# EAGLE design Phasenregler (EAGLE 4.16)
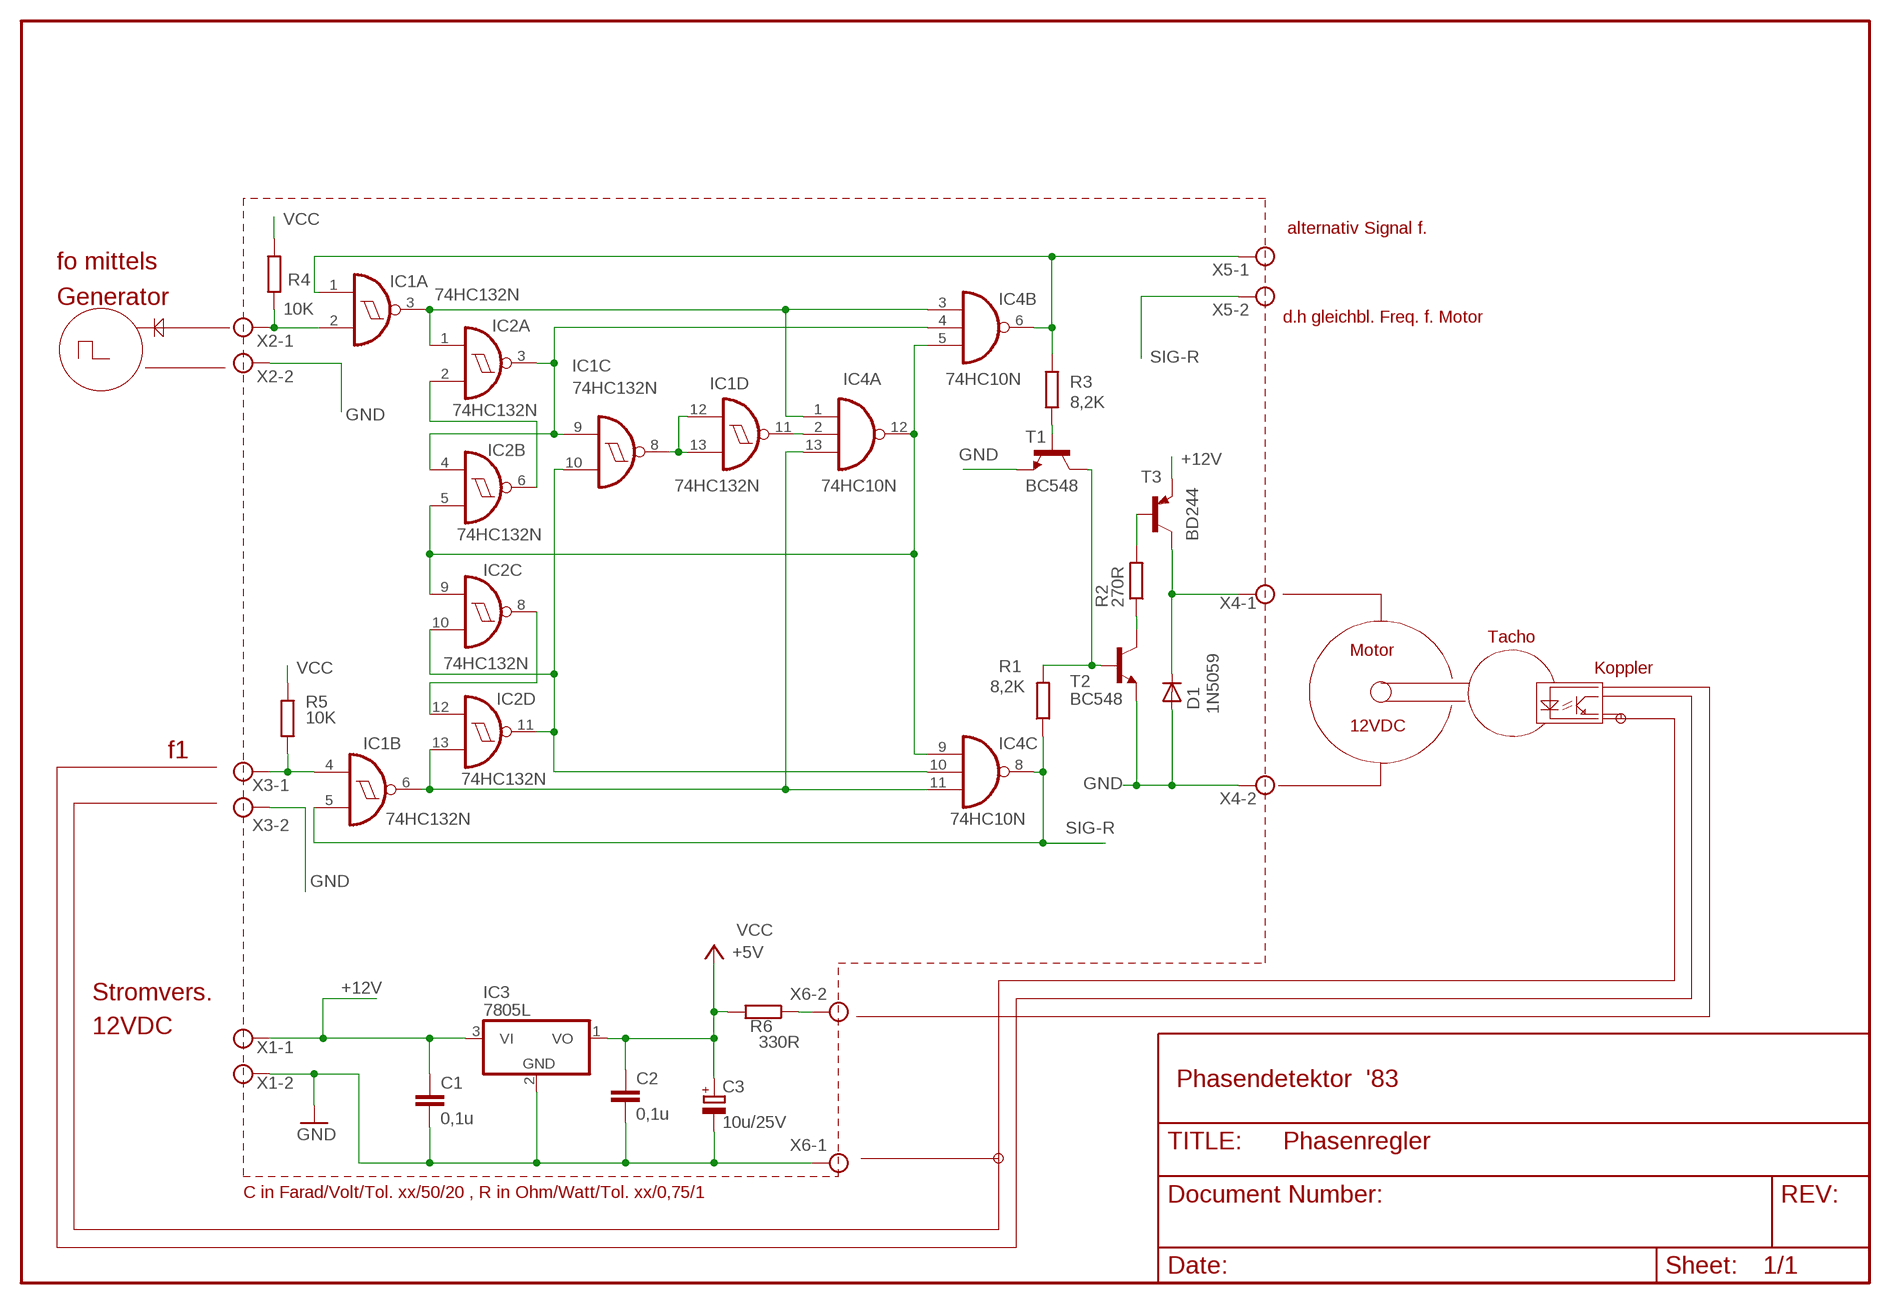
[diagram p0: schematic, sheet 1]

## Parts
C1  0,1u  C-EU050-025X075  [C050-025X075]
C2  0,1u  C-EU050-025X075  [C050-025X075]
C3  10u/25V  CPOL-EUE2-5  [E2-5]
D1  1N5059  [DO204-10]
IC1  74HC132N  [DIL14]
IC2  74HC132N  [DIL14]
IC3  7805L  [TO92]
IC4  74HC10N  [DIL14]
R1  8,2K  R-EU_0207/10  [0207/10]
R2  270R  R-EU_0207/10  [0207/10]
R3  8,2K  R-EU_0207/10  [0207/10]
R4  10K  R-EU_0207/10  [0207/10]
R5  10K  R-EU_0207/10  [0207/10]
R6  330R  R-EU_0207/10  [0207/10]
T1  BC548  [TO92]
T2  BC548  [TO92]
T3  BD244  [TO220]
X1  AK300/2  [AK300/2]
X2  AK300/2  [AK300/2]
X3  AK300/2  [AK300/2]
X4  AK300/2  [AK300/2]
X5  AK300/2  [AK300/2]
X6  AK300/2  [AK300/2]

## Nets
+12V: C1.1 IC3.3(VI) T3.3(E) X1.1
GND: C1.2 C2.2 C3.- D1.A IC3.2(GND) T1.1(E) T2.1(E) X1.2 X2.2 X3.2 X4.2 X6.1
N$1: IC2.2(A:I1) IC2.6(B:O)
N$2: IC1.9(C:I0) IC2.3(A:O) IC2.4(B:I0) IC4.4(B:I1)
N$3: IC2.5(B:I1) IC2.9(C:I0) IC4.5(B:I2) IC4.9(C:I0) IC4.12(A:O)
N$4: IC1.8(C:O) IC1.12(D:I0) IC1.13(D:I1)
N$5: IC2.8(C:O) IC2.12(D:I0)
N$6: IC1.10(C:I1) IC2.10(C:I1) IC2.11(D:O) IC4.10(C:I1)
N$7: IC1.11(D:O) IC4.2(A:I1)
N$8: IC1.3(A:O) IC2.1(A:I0) IC4.1(A:I0) IC4.3(B:I0)
N$9: IC1.6(B:O) IC2.13(D:I1) IC4.11(C:I2) IC4.13(A:I2)
N$11: IC1.1(A:I0) IC4.6(B:O) R3.2 X5.1
N$13: R1.2 T1.3(C) T2.2(B)
N$14: R2.1 T2.3(C)
N$15: R2.2 T3.1(B)
N$16: R3.1 T1.2(B)
N$17: IC1.4(B:I0) R5.1 X3.1
N$18: IC1.2(A:I1) R4.1 X2.1
N$19: D1.C T3.2(C) X4.1
N$20: R6.1 X6.2
SIG-R: IC1.5(B:I1) IC4.8(C:O) R1.1 X5.2
VCC: C2.1 C3.+ IC3.1(VO) R4.2 R5.2 R6.2 ; supply symbol labelled +5V

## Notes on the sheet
- alternativ Signal f.
- fo mittels
- Generator
- d.h gleichbl. Freq. f. Motor
- Tacho
- Motor
- Koppler
- 12VDC
- f1
- Stromvers.
- 12VDC
- Phasendetektor  '83
- C in Farad/Volt/Tol. xx/50/20 , R in Ohm/Watt/Tol. xx/0,75/1

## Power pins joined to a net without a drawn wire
GND: IC1.7(P:GND) IC2.7(P:GND) IC4.7(P:GND)
VCC: IC1.14(P:VCC) IC2.14(P:VCC) IC4.14(P:VCC)

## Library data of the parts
C1 C2 = rcl:C-EU: CAPACITOR, European symbol
C3 = rcl:CPOL-EU: POLARIZED CAPACITOR, European symbol
D1 = diode:1N5059: DIODE
IC1 IC2 = 74xx-eu:74*132: Quad 2-input NAND schmitt trigger
IC3 = linear:78*: Positive VOLTAGE REGULATOR Source: http://cache.national.com/ds/LM/LM78L05.pdf http://www.fairchildsemi.com/ds/LM/LM7805.pdf
IC4 = 74xx-eu:74*10: Triple 3-input NAND gate
R1-R6 = rcl:R-EU_: RESISTOR, European symbol
T1 T2 = transistor-mix:BC548: NPN TRANSISTOR
T3 = transistor-mix:BD244: PNP TRANSISTOR
X1-X6 = con-ptr500:AK300/2: CONNECTOR

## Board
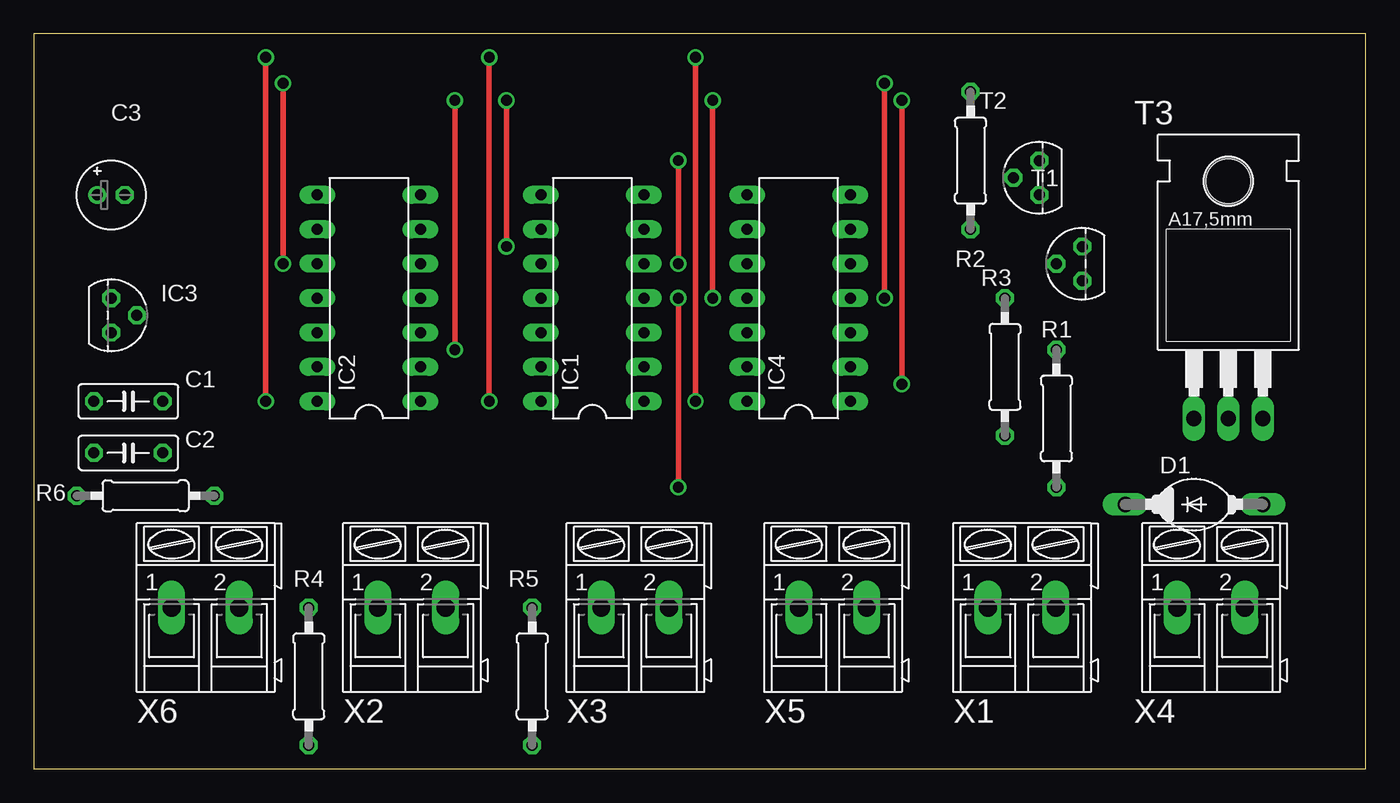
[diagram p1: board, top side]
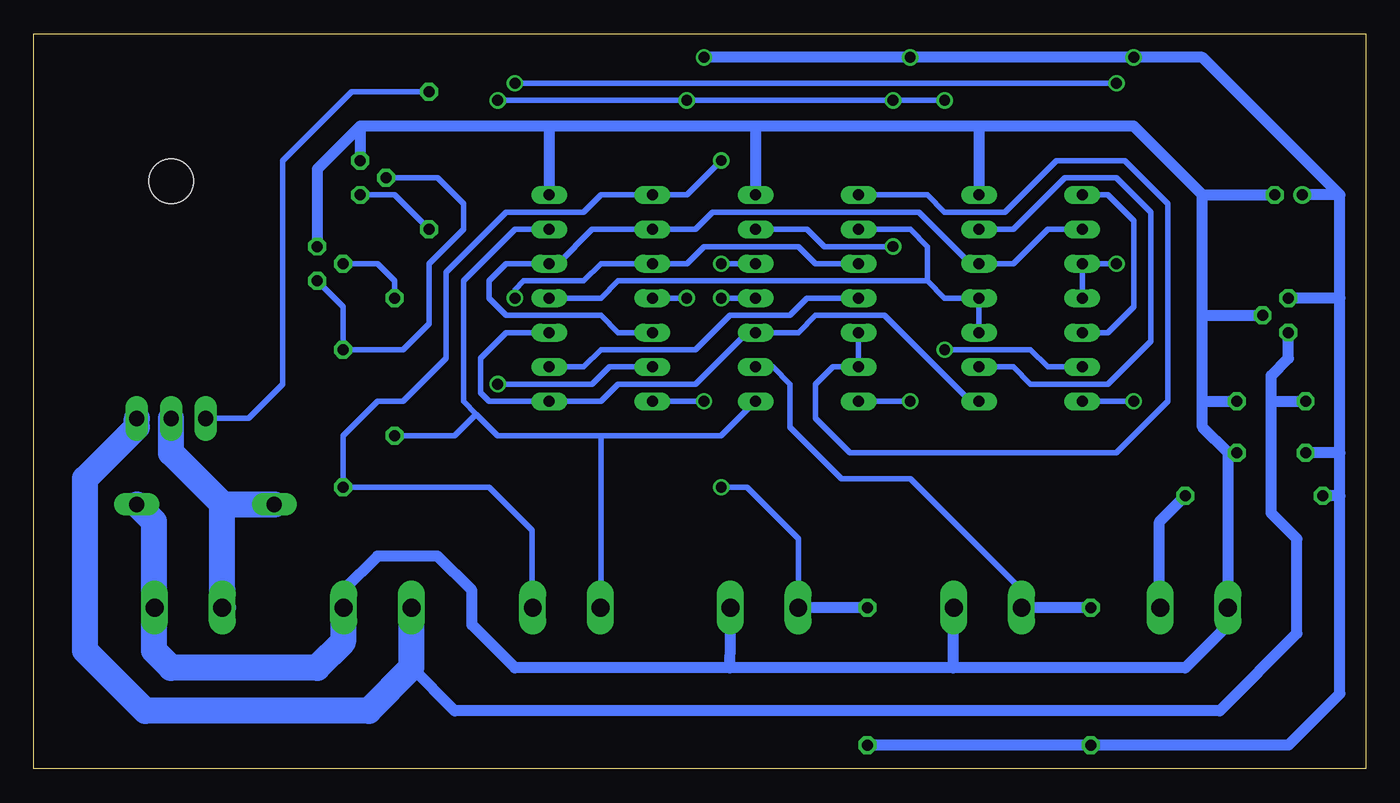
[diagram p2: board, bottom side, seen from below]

Size 98.41 x 54.28 mm. Coordinates in mm from the lower left corner, seen from the top.
Outline: 0,0 98.41,0 98.41,54.28 0,54.28 0,0
Copper layers (1*16): Top 0.035mm / dielectric 1.5mm / Bottom 0.035mm
Design rules "default": minimum track width 10mil, minimum drill 24mil, track to track 8mil, track to pad 8mil, pad to pad 8mil, via to via 8mil, smd to smd 8mil, copper to edge 40mil, drill to drill 8mil, minimum pad ring 10mil, minimum via ring 8mil, stop-mask expansion 4mil, vias tented up to drill 0mil, thermal gap 10mil

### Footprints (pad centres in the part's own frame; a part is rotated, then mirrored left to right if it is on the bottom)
C050-025X075 = drill 0.813 octagon: 1 -2.54,0; 2 2.54,0
E2-5 = drill 0.813 pad 1.27 round: + -1.016,0 | drill 0.813 pad 1.27 octagon: - 1.016,0
DO204-10 = drill 1.118 long: A 5.08,0; C -5.08,0
DIL14 = drill 0.813 long: 1 -7.62,-3.81; 2 -5.08,-3.81; 3 -2.54,-3.81; 4 0,-3.81; 5 2.54,-3.81; 6 5.08,-3.81; 7 7.62,-3.81; 8 7.62,3.81; 9 5.08,3.81; 10 2.54,3.81; 11 0,3.81; 12 -2.54,3.81; 13 -5.08,3.81; 14 -7.62,3.81
TO92 = drill 0.813 octagon: 1 -1.27,0; 2 0,1.905; 3 1.27,0
0207/10 = drill 0.813 octagon: 1 -5.08,0; 2 5.08,0
TO92' = drill 0.813 octagon: 1 1.27,0; 2 0,1.905; 3 -1.27,0
TO220 = drill 1.118 long: 1 -2.54,-6.35; 2 0,-6.35; 3 2.54,-6.35 | hole 3.302: 0,11.176
AK300/2 = drill 1.321 long: 1 -2.515,0; 2 2.489,0

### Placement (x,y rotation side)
C1  6.98,27.14 0 top
C2  6.98,23.33 0 top
C3  5.71,42.38 0 top
D1  85.72,19.52 0 top
IC1  41.27,34.76 90 top
IC2  24.76,34.76 90 top
IC3  5.71,33.49 270 top
IC4  56.51,34.76 90 top
R1  75.56,25.87 90 top
R2  69.21,44.92 90 top
R3  71.75,29.68 270 top
R4  20.31,6.82 270 top
R5  36.83,6.82 270 top
R6  8.25,20.15 180 top
T1  BC548  [TO92']  77.46,37.3 90 top
T2  BC548  [TO92']  74.29,43.65 90 top
T3  88.26,32.22 0 top
X1  73.02,11.9 0 top
X2  27.93,11.9 0 top
X3  44.45,11.9 0 top
X4  86.99,11.9 0 top
X5  59.05,11.9 0 top
X6  12.7,11.9 0 top

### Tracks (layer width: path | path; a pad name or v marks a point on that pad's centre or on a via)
+12V
  Bottom 0.813: IC3.3 5.71,30.31 6.98,29.04 6.98,27.14 | 6.98,27.14 C1.1 | 6.98,27.14 6.98,18.88 5.08,16.98 5.08,10 10.79,4.28 67.3,4.28 70.5,7.48
  Bottom 1.93: T3.3 90.8,25.23 94.61,21.42 94.61,8.73 90.16,4.28 73.66,4.28 70.5,7.48 X1.1
GND
  Bottom 0.813: 10.16,11.9 10.16,10.63 13.33,7.46 30.47,7.46 | 46.98,7.46 46.93,9.41 X3.2 | 30.47,7.46 46.98,7.46 | 10.16,23.33 C2.2 | 28.57,47.46 IC2.7 | 28.57,47.46 17.14,47.46 12.06,42.38 | 45.08,47.46 IC1.7 | 28.57,47.46 45.08,47.46 | 60.32,47.46 IC4.7 | 45.08,47.46 60.32,47.46 | 74.29,47.46 77.46,44.28 T1.1 | 60.32,47.46 74.29,47.46 | 12.06,33.49 12.06,42.38 | 12.06,33.49 IC3.2 | 12.06,42.38 C3.- | 12.06,27.14 C1.2 | 12.06,27.14 12.06,25.23 10.16,23.33 | 12.06,27.14 12.06,33.49 | 74.29,47.46 T2.1 | X6.1 10.16,11.9 | 10.16,11.9 10.16,23.33 | X2.2 30.47,11.9 30.47,7.46 | 46.98,7.46 62.86,7.46 66.03,10.63 66.03,13.17 68.57,15.71 73.02,15.71 75.56,13.17 75.56,11.9 X1.2
  Bottom 1.93: 75.56,11.9 75.56,9.36 77.46,7.46 88.26,7.46 89.53,8.73 89.53,11.9 | D1.A 89.53,18.25 89.53,11.9 | 89.53,11.9 X4.2
N$1
  Bottom 0.406: IC2.6 26.03,39.84 22.22,43.65 18.41,43.65 15.87,41.11 15.87,31.58 19.04,28.41 24.76,28.41 26.03,29.68 IC2.2
N$2
  Bottom 0.406: IC2.3 IC2.4 31.11,34.76 32.38,36.03 | 32.38,36.03 32.38,38.57 33.65,39.84 IC1.9 | IC4.4 56.51,34.76 55.24,36.03 32.38,36.03
N$3
  Bottom 0.406: IC2.9 23.49,39.84 26.03,37.3 IC2.5 29.2,37.3 33.02,41.11 48.26,41.11 49.53,39.84 IC4.9 57.15,39.84 59.69,37.3 IC4.5 63.5,37.3 64.77,36.03 64.77,34.76 63.5,33.49 56.51,33.49 55.24,32.22 IC4.12
N$4
  Bottom 0.406: IC1.8 32.38,42.38 31.11,41.11 26.66,41.11 22.86,44.92 17.77,44.92 14.6,41.74 14.6,27.14 18.41,23.33 38.1,23.33 40.64,25.87 40.64,28.41 39.37,29.68 IC1.13 IC1.12
N$5
  Bottom 0.406: IC2.8 19.04,42.38 17.14,40.48 17.14,34.12 19.04,32.22 IC2.12
N$6  (via drill 0.8)
  Top 0.406: v18.41,37.3 v18.41,50.63 | v62.86,50.63 v62.86,34.76
  Bottom 0.406: IC2.11 IC2.10 v18.41,37.3 | IC1.10 40.64,37.3 41.91,38.57 48.89,38.57 50.16,37.3 IC4.10 56.51,37.3 57.78,36.03 62.23,36.03 62.86,35.39 v62.86,34.76 | v18.41,50.63 v62.86,50.63
N$7
  Bottom 0.406: IC1.11 41.27,34.76 42.54,33.49 46.98,33.49 49.53,30.95 56.51,30.95 57.78,29.68 IC4.2
N$8
  Bottom 0.406: IC2.1 29.2,27.14 35.55,33.49 40.64,33.49 41.91,32.22 IC1.3 45.72,32.22 49.53,28.41 55.24,28.41 56.51,27.14 IC4.1 64.77,27.14 65.4,27.77 65.4,30.31 63.5,32.22 IC4.3
N$9  (via drill 0.8)
  Top 0.406: v50.16,49.37 v50.16,34.76 | v34.92,49.37 v34.92,38.57 | v31.11,30.95 v31.11,49.37 | v64.13,49.37 v64.13,28.41
  Bottom 0.406: IC2.13 23.49,29.68 24.76,30.95 v31.11,30.95 | v50.16,34.76 IC4.11 | v34.92,38.57 40,38.57 41.27,39.84 IC1.6 | v31.11,49.37 v34.92,49.37 v50.16,49.37 v64.13,49.37 | IC4.13 55.88,29.68 57.15,28.41 v64.13,28.41
N$11
  Bottom 0.406: IC4.6 62.86,39.84 66.67,36.03 66.67,27.14 65.72,26.19 | IC1.1 47.62,24.6 56.51,24.6 | 56.51,24.6 64.13,24.6 65.72,26.19 | X5.1 56.51,11.9 56.51,24.6 | R3.2 67.3,24.6 65.72,26.19
N$13
  Bottom 0.406: T2.2 68.57,43.65 66.67,41.74 66.67,39.84 69.21,37.3 69.21,32.85 71.11,30.95 R1.2 75.56,34.12 T1.3
N$14
  Bottom 0.406: R2.1 71.75,42.38 T2.3
N$15
  Bottom 0.406: R2.2 74.92,50 80,44.92 80,28.41 82.55,25.87 T3.1
N$16
  Bottom 0.406: T1.2 73.02,37.3 71.75,36.03 R3.1
N$17  (via drill 0.8)
  Top 0.406: v47.62,20.79 v47.62,34.76
  Bottom 0.254: 41.91,11.9 X3.1
  Bottom 0.406: v47.62,34.76 IC1.4 | v47.62,20.79 45.72,20.79 41.91,16.98 41.91,11.9
  Bottom 0.813: R5.1 41.91,11.9
N$18
  Bottom 0.406: IC1.2 43.81,29.68 42.54,28.41 42.54,25.23 38.73,21.42 33.65,21.42 25.39,13.17 25.39,11.9
  Bottom 0.813: R4.1 25.39,11.9 X2.1
N$19
  Bottom 1.93: X4.1 84.45,11.9 84.47,13.2 84.47,19.49 84.45,19.52 | T3.2 88.26,23.33 84.45,19.52 | 84.45,19.52 D1.C
N$20
  Bottom 0.813: R6.1 15.24,18.25 15.24,11.9 X6.2
SIG-R  (via drill 0.8)
  Top 0.406: v47.62,44.92 v47.62,37.3
  Bottom 0.406: v47.62,44.92 50.16,42.38 IC4.8 56.51,42.38 57.78,41.11 63.5,41.11 67.94,36.66 67.94,30.31 71.11,27.14 73.02,27.14 75.56,24.6 R1.1 64.77,20.79 61.59,17.61 61.59,11.9 X5.2 | v47.62,37.3 IC1.5
VCC  (via drill 0.8)
  Top 0.406: v17.14,52.54 v17.14,27.14 | v33.65,52.54 v33.65,27.14 | v48.89,52.54 v48.89,27.14
  Bottom 0.406: v17.14,27.14 IC2.14 | v33.65,27.14 IC1.14 | v48.89,27.14 IC4.14
  Bottom 0.813: 1.9,34.76 IC3.1 | 1.9,34.76 1.9,42.38 | 1.9,42.38 C3.+ | 1.9,23.33 C2.1 | 1.9,20.15 1.9,23.33 | 1.9,20.15 R6.2 | 1.9,23.33 1.9,34.76 | 1.9,42.38 12.06,52.54 v17.14,52.54 v33.65,52.54 v48.89,52.54 | R5.2 R4.2 5.71,1.74 1.9,5.55 1.9,20.15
